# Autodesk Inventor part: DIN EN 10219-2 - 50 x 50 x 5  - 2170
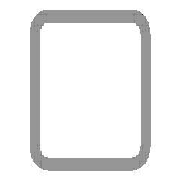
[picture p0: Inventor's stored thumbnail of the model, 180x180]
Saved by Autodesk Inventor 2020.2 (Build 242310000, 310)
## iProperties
Created: 2019-10
Part Number: DIN EN 10219-2 - 50 x 50 x 5  - 2170
Material: Stahl, weich
Description: Kaltgeformte, geschweißte Baustahl-Hohlprofile aus unlegiertem Feinkorn-Baustahl
Document SubType Name: Modeling
Standard: DIN
Designer: lutzd
Standard Revision: 2006-07
Standards Organization: DIN
Language: de-DE
Size Designation: 50 x 50 x 5
Categories: <MemberInstance><Categories><Category DisplayName="Profile" InternalName="089c4875-fa83-4c05-b084-43b9cc11f5ed" Mnemonic="GRDR"><CategoryParameter DisplayName="
Stock Number: 50 x 50 x 5
Mass: 14220.7 g
Surface Area: 7273.39 cm^2
Volume: 1811.56 cm^3
Density: 7.85 g/cm^3
Appearance: Semi-Polished(8)
IsCustomPart: 1
G_L: 2170,000 mm
G_W: 50,000 mm
G_H: 50,000 mm
Mass: 14,221 kg
VLT_Material: Stahl, weich
DocNumber: ADSK-014382
Folder: .
Dimensions: 50x50x2170 mm
_CCFamilyMember: 16
_CCFamilyDisplayName: DIN EN 10219-2 (Quadratisches Hohlprofil - Kaltgeformt) - Kaltgeformte, geschweißte Baustahl-Hohlprofile aus unlegiertem Feinkorn-Baustahl
_FrameMemberDoc: Frame Member File
_Version: 15.0.0
_GetPNFromCC: 1
Title: Profil-Bauteil
Author: lutzd
Revision Number: -
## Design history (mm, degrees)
node "Startebene"
node "Endebene"
sketch "Skizze"
  geometry: L1 (-25, -15)-(-25, 15); L2 (-15, 25)-(15, 25); L3 (25, 15)-(25, -15); L4 (15, -25)-(-15, -25); L5 (-15, 20)-(15, 20); L6 (20, 15)-(20, -15); L7 (15, -20)-(-15, -20); L8 (-20, -15)-(-20, 15); L9 (0, 37.899)-(0, -37.899) reference; L10 (-37.899, 0)-(37.899, 0) reference; A1 r 10 centre (-15, -15) between (-25, -15) and (-15, -25); A2 r 10 centre (-15, 15) between (-15, 25) and (-25, 15); A3 r 10 centre (15, 15) between (25, 15) and (15, 25); A4 r 10 centre (15, -15) between (15, -25) and (25, -15); A5 r 5 centre (-15, 15) between (-15, 20) and (-20, 15); A6 r 5 centre (15, 15) between (20, 15) and (15, 20); A7 r 5 centre (15, -15) between (15, -20) and (20, -15); A8 r 5 centre (-15, -15) between (-20, -15) and (-15, -20)
  constraints: 16 end point, 16 point on circle, 8 centre point, 8 tangent, 4 parallel, 3 equal radius, 2 perpendicular, 7 other
  dimensions: "d7" = 10 radius of A1 (= G_IR); "d10" = 50 distance between parallel lines of L2 L4 (= G_H); "d11" = 50 distance between parallel lines of L1 L3 (= G_W); "d12" = 5 distance between parallel lines of L3 L6 (= G_T); "d15" = 25 distance between parallel lines of L2 L10 (= 0.5 x d10); "d16" = 25 distance between parallel lines of L9 L3 (= 0.5 x d11)
extrude "Körper" new body sketch "Skizze" stored distance "d3" = 2170 (= G_L); taper "d4" = 0 deg
node "Driven Length"
  sketch "Sketch3"
    geometry: L1 (0, 0)-(10, 0) reference
    constraints: 2 end point, 1 horizontal
  workplane "Work Plane3"
  sketch "Sketch4"
    geometry: L1 (-2, 0)-(12, 0) reference; L2 (-2, 2170)-(12, 2170) reference
    dimensions: "d18" = 2170 distance between parallel lines of L1 L2 (derived)
sketch "Skizze5"
  geometry: L1 (0, -30)-(0, 0) reference; L2 (1543, -15)-(1862, -15); 11 further points; 1 other entity
  constraints: 2 coincident, 2 end point, 1 horizontal, 1 point on line, 10 other
  dimensions: "d19" = 66 distance of point (553, -15) point (487, -15); "d20" = 66 distance of point (1477, -15) point (1543, -15); "d21" = 1543 distance of point (0, -15) point (1543, -15); "d22" = 990 distance of point (553, -15) L2.start; "d30" = 310 distance of point (0, -15) point (310, -15); "d31" = 319 distance of L2.start L2.end; "d32" = 282 distance of point (1862, -15) point (1580, -15); "d33" = 39.5 distance of point (553, -15) point (592.5, -15); "d34" = 282 distance of point (874.5, -15) point (592.5, -15); "d35" = 245 distance of L2.start point (1298, -15)
hole "Bohrung1" sketch "Skizze5" at (1543, -15), (1477, -15), (553, -15), (487, -15), (310, -15), (592.5, -15), (874.5, -15), (1298, -15), (1580, -15), (1862, -15) diameter "d23" = 6.647; stored, may be unused: countersink angle "d27" = 90 deg, drill point angle "d29" = 118 deg; dims "d24" = 16, "d25" = 4, "d26" = 2, "d28" = 8
body "Solid1"
other parameters: "G_W" = 50 [user parameter; used in 1 equation term], "G_H" = 50 [user parameter; used in 1 equation term], "G_T" = 5 [user parameter; used in 1 equation term], "G_IR" = 10 [user parameter; used in 1 equation term], "G_L" = 2170 (= d18) [user parameter; used in 1 equation term], "G_OFFSET_START" = 0 [user parameter; used in 1 equation term], "G_OFFSET_END" = 0 [user parameter; used in 1 equation term], "d13" = 0 (computed from G_OFFSET_START), "d17" = 90 deg
